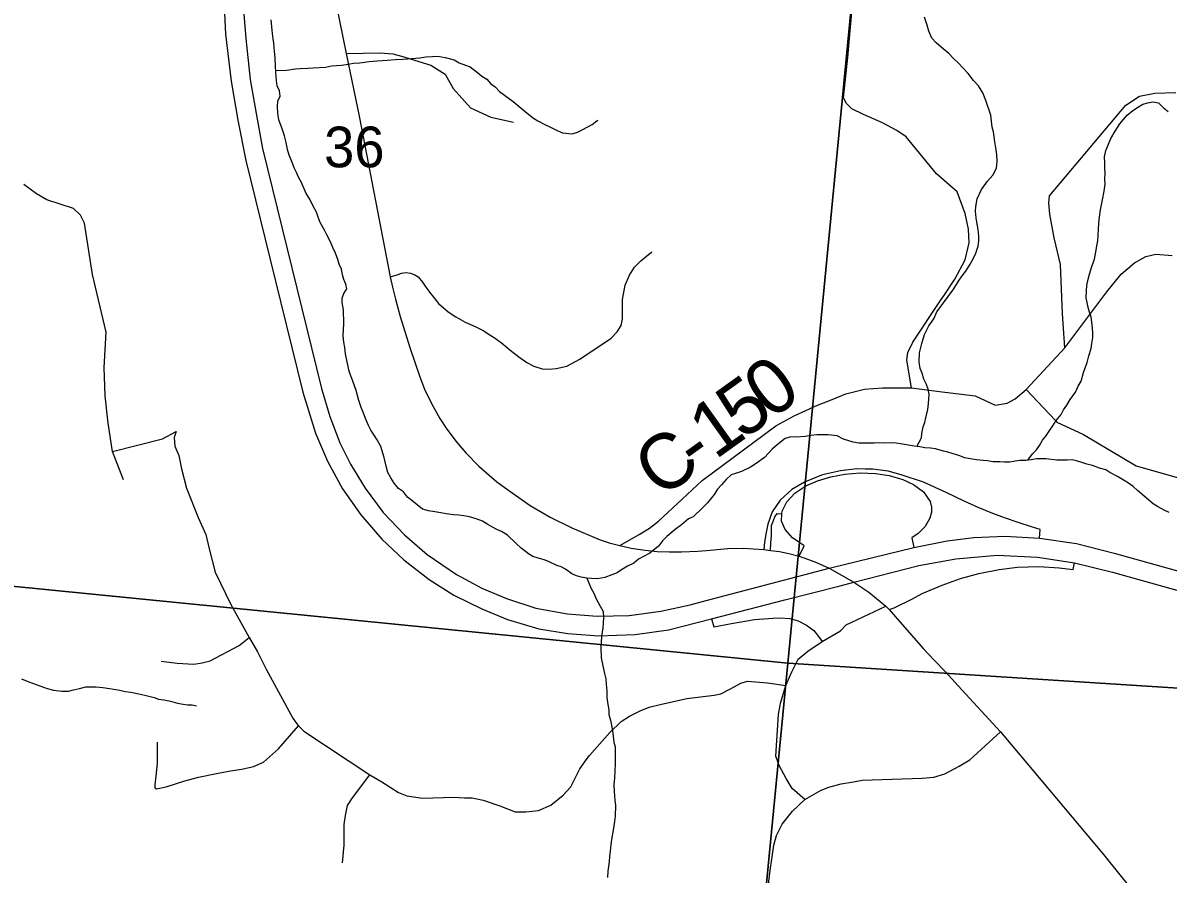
# Model space of a CAD drawing. Extents: x 0 to 34, y 0 to 22.
# Drawn here: x 5.48 to 6.66, y 15.894 to 16.77 of the extents above; entities that cross this region are included whole.
import ezdxf

# ---------------------------------------------------------------- set-up
doc = ezdxf.new("R2010")
doc.units = 0
for name, color, linetype in [('GM_X_County_Road', 7, 'Continuous'), ('GM_X_County_Road_Text', 7, 'Continuous'), ('GM_X_Interchange_Ramps', 7, 'Continuous'), ('GM_X_Interstate_Route', 7, 'Continuous'), ('GM_X_Minor_River', 7, 'Continuous'), ('GM_X_Section', 7, 'Continuous'), ('GM_X_Section_Text', 7, 'Continuous'), ('GM_X_Township_Road', 7, 'Continuous'), ('GM_X_US_Route', 7, 'Continuous')]:
    doc.layers.add(name, color=color, linetype=linetype)

msp = doc.modelspace()

# ---------------------------------------------------------------- linework, layer by layer
at = {"layer": 'GM_X_County_Road'}
for p, q in [((6.5133, 16.3926), (6.5435, 16.3606)), ((6.2433, 16.2278), (6.2501, 16.227))]:
    msp.add_line(p, q, dxfattribs=at)
for points in [[(5.7859, 16.8717), (5.8131, 16.7386), (5.8262, 16.674), (5.8583, 16.5087), (5.8607, 16.498), (5.8638, 16.4855), (5.8685, 16.4679), (5.8785, 16.436), (5.8888, 16.4057), (5.8937, 16.3929), (5.8977, 16.3843), (5.9025, 16.375), (5.9094, 16.3629), (5.9158, 16.3527), (5.9258, 16.3393), (5.9362, 16.3274), (5.9495, 16.3137), (5.968, 16.2976), (5.9814, 16.2878), (6.0025, 16.2733), (6.023, 16.2611), (6.0453, 16.2503), (6.0746, 16.2378), (6.0838, 16.2346), (6.0947, 16.232), (6.1065, 16.2292), (6.121, 16.2271), (6.1334, 16.2259), (6.1455, 16.2253), (6.1585, 16.2254), (6.1752, 16.2262), (6.1879, 16.2272), (6.2061, 16.2289), (6.2218, 16.2292), (6.2433, 16.2278)], [(6.5531, 16.4354), (6.5509, 16.4708), (6.5487, 16.5214), (6.5421, 16.5489), (6.5379, 16.5733), (6.5368, 16.5844), (6.5374, 16.592), (6.6159, 16.6855), (6.6302, 16.6945), (6.6459, 16.6978), (6.6675, 16.6983)], [(6.5531, 16.4354), (6.5964, 16.4932), (6.6113, 16.5114), (6.625, 16.5231), (6.6366, 16.5295), (6.6469, 16.5319), (6.6639, 16.5306)], [(6.3073, 16.3799), (6.3135, 16.3824), (6.3275, 16.388), (6.3467, 16.3928), (6.3655, 16.3944), (6.3954, 16.3944), (6.4242, 16.3904), (6.4609, 16.386), (6.4815, 16.3766), (6.4937, 16.3785), (6.5022, 16.3831), (6.5133, 16.3926), (6.5531, 16.4354)], [(6.0947, 16.232), (6.1148, 16.2434), (6.1254, 16.2499), (6.1347, 16.2571), (6.159, 16.2797), (6.1797, 16.2989), (6.2329, 16.3384), (6.2556, 16.3552), (6.2744, 16.3656), (6.2984, 16.3764), (6.3073, 16.3799)], [(6.5435, 16.3606), (6.545, 16.359), (6.5723, 16.3462), (6.6266, 16.314), (6.6726, 16.3011)], [(6.2501, 16.227), (6.2594, 16.2257), (6.2688, 16.2237), (6.2794, 16.221), (6.2893, 16.2177), (6.2973, 16.2146), (6.3104, 16.2087), (6.3359, 16.1942), (6.3512, 16.1838), (6.3687, 16.1696), (6.3722, 16.166), (6.381, 16.1561), (6.4076, 16.1255), (6.419, 16.1137)], [(6.3032, 16.133), (6.3223, 16.1442), (6.3281, 16.1503), (6.3687, 16.1696)], [(6.26, 16.0675), (6.2603, 16.0695), (6.2658, 16.0877), (6.2719, 16.1019), (6.2787, 16.115), (6.2884, 16.1231), (6.3032, 16.133)], [(6.419, 16.1137), (6.4303, 16.1019), (6.4435, 16.0876), (6.4868, 16.04), (6.5286, 15.9906), (6.593, 15.914), (6.6126, 15.8896), (6.6359, 15.861), (6.6545, 15.8376), (6.675, 15.8077)], [(6.2854, 15.9703), (6.2722, 15.9818), (6.2662, 15.9921), (6.2591, 16.0054), (6.2554, 16.0151), (6.2582, 16.0581), (6.26, 16.0675)], [(6.2854, 15.9703), (6.3024, 15.98), (6.3101, 15.9833), (6.323, 15.9865), (6.3357, 15.9888), (6.3445, 15.9904), (6.4064, 15.9923), (6.4182, 15.9934), (6.4297, 15.9969), (6.4443, 16.0047), (6.4554, 16.0112), (6.4868, 16.04)], [(6.2452, 15.8706), (6.2479, 15.883), (6.2495, 15.8948), (6.2517, 15.9115), (6.2536, 15.9234), (6.2562, 15.9334), (6.2622, 15.9451), (6.2726, 15.9583), (6.2854, 15.9703)]]:
    msp.add_lwpolyline(points, dxfattribs=at)
at = {"layer": 'GM_X_Interchange_Ramps'}
for points in [[(6.3066, 16.3053), (6.3025, 16.3044), (6.2851, 16.2971), (6.272, 16.2896), (6.26, 16.2788), (6.2519, 16.2666), (6.2472, 16.2541), (6.2456, 16.2453), (6.244, 16.2353), (6.2433, 16.2278)], [(6.2794, 16.221), (6.2848, 16.2318), (6.2728, 16.2399), (6.2651, 16.2483), (6.2615, 16.2572), (6.2618, 16.2646), (6.2619, 16.2672), (6.2668, 16.2771), (6.2751, 16.2857), (6.2866, 16.2933), (6.2983, 16.2985), (6.3121, 16.3028), (6.3266, 16.3055), (6.3425, 16.3067), (6.3583, 16.3061), (6.3722, 16.3041), (6.3863, 16.3001), (6.3973, 16.2949), (6.4078, 16.2871), (6.4144, 16.2773), (6.4159, 16.2713), (6.4159, 16.2662), (6.4143, 16.26), (6.4093, 16.2516), (6.402, 16.2443), (6.3956, 16.2399), (6.3976, 16.2299)], [(6.3474, 16.3107), (6.3391, 16.3108), (6.322, 16.309), (6.3066, 16.3053)], [(6.527, 16.2397), (6.5279, 16.2486), (6.5188, 16.2512), (6.505, 16.2556), (6.4911, 16.2604), (6.479, 16.265), (6.464, 16.2711), (6.4494, 16.2776), (6.4309, 16.2865), (6.4077, 16.2971), (6.3847, 16.3049), (6.3712, 16.3085), (6.3556, 16.3105), (6.3474, 16.3107)], [(6.2501, 16.227), (6.2505, 16.2349), (6.2509, 16.242), (6.2509, 16.2474), (6.2512, 16.2525), (6.2523, 16.256), (6.2545, 16.2616), (6.257, 16.2651), (6.2618, 16.2646)], [(6.3722, 16.166), (6.3774, 16.1679), (6.3955, 16.1769), (6.4062, 16.1826), (6.4269, 16.1911), (6.4459, 16.198), (6.4647, 16.203), (6.4855, 16.2074), (6.5044, 16.2097), (6.5263, 16.2103), (6.5473, 16.2091), (6.5619, 16.2072), (6.5632, 16.2143)], [(6.1891, 16.1566), (6.1916, 16.1484), (6.21, 16.1516), (6.2337, 16.1557), (6.248, 16.1569), (6.2528, 16.1571)], [(6.2528, 16.1571), (6.2601, 16.1574), (6.27, 16.1567), (6.2785, 16.1544), (6.287, 16.15), (6.2946, 16.1443), (6.2986, 16.1398), (6.3032, 16.133)]]:
    msp.add_lwpolyline(points, dxfattribs=at)
at = {"layer": 'GM_X_Interstate_Route'}
for p, q in [((6.2649, 16.1761), (6.3217, 16.1906)), ((6.1891, 16.1566), (6.2649, 16.1761))]:
    msp.add_line(p, q, dxfattribs=at)
for points in [[(5.5746, 17.316), (5.6012, 17.2831), (5.6128, 17.2649), (5.6269, 17.2407), (5.6435, 17.2072), (5.6512, 17.1853), (5.6546, 17.1738), (5.658, 17.1627), (5.6648, 17.135), (5.6694, 17.1059), (5.6727, 17.0756), (5.6747, 17.0368), (5.6777, 16.9778), (5.6863, 16.8093), (5.6887, 16.7584), (5.6946, 16.7102), (5.7012, 16.6698), (5.7095, 16.6284), (5.7343, 16.528)], [(5.7052, 16.8084), (5.7095, 16.754), (5.7142, 16.7117), (5.7201, 16.6768), (5.7269, 16.6406), (5.7874, 16.3937), (5.7962, 16.3649), (5.8065, 16.3377), (5.8175, 16.3156), (5.8324, 16.291), (5.8512, 16.266), (5.8729, 16.243), (5.8965, 16.2226), (5.9267, 16.202), (5.9526, 16.1879), (5.9782, 16.1774), (6.0083, 16.1675), (6.041, 16.1616), (6.0714, 16.1592), (6.1043, 16.1598), (6.137, 16.1645), (6.1673, 16.1708), (6.1838, 16.1752), (6.3104, 16.2087), (6.3976, 16.2299), (6.432, 16.2368), (6.4594, 16.2403), (6.4919, 16.2417), (6.527, 16.2397), (6.5651, 16.2339), (6.6042, 16.2241), (6.6816, 16.2026)], [(5.7343, 16.528), (5.7683, 16.3898), (5.7812, 16.3476), (5.7938, 16.3187), (5.8093, 16.2904), (5.828, 16.2634), (5.8497, 16.2386), (5.8725, 16.2171), (5.8986, 16.197), (5.924, 16.1807), (5.9528, 16.1667), (5.9791, 16.1559), (6.0115, 16.1463), (6.0414, 16.1413), (6.0727, 16.1391), (6.1105, 16.1404), (6.1449, 16.1452), (6.1891, 16.1566)], [(6.3217, 16.1906), (6.3359, 16.1942), (6.4029, 16.2113), (6.4411, 16.2183), (6.4834, 16.2219), (6.5251, 16.2201), (6.5632, 16.2143)], [(6.5632, 16.2143), (6.6023, 16.2045), (6.6797, 16.183)]]:
    msp.add_lwpolyline(points, dxfattribs=at)
at = {"layer": 'GM_X_Minor_River'}
for points in [[(6.4007, 16.334), (6.4055, 16.3427), (6.406, 16.3472), (6.4074, 16.354), (6.409, 16.3585), (6.41, 16.3634), (6.4122, 16.3721), (6.4127, 16.3782), (6.4133, 16.3827), (6.4135, 16.3876), (6.4125, 16.393), (6.4108, 16.3976), (6.4079, 16.4034), (6.4062, 16.4095), (6.4041, 16.4142), (6.4032, 16.421), (6.4035, 16.4305), (6.4058, 16.44), (6.4087, 16.4493), (6.4132, 16.4583), (6.4184, 16.4654), (6.4213, 16.4725), (6.4261, 16.4791), (6.4329, 16.4884), (6.4388, 16.4962), (6.4437, 16.504), (6.4476, 16.5096), (6.4512, 16.5144), (6.4557, 16.5218), (6.4589, 16.527), (6.4614, 16.533), (6.4639, 16.5401), (6.4648, 16.5458), (6.4646, 16.5504), (6.4641, 16.5572), (6.4625, 16.5649), (6.4619, 16.5695), (6.4613, 16.5763), (6.4615, 16.5809), (6.4629, 16.5888), (6.4674, 16.5985), (6.4734, 16.6071), (6.4789, 16.6133), (6.483, 16.6204), (6.4836, 16.6272), (6.4831, 16.6345), (6.4825, 16.6394), (6.4812, 16.6475), (6.4797, 16.6578), (6.4784, 16.6628), (6.4769, 16.675), (6.4717, 16.6903), (6.4686, 16.6981), (6.4643, 16.7054), (6.4591, 16.7109), (6.4537, 16.7179), (6.4434, 16.7289), (6.4386, 16.7333), (6.4339, 16.7384), (6.4258, 16.7451), (6.4206, 16.7495), (6.4162, 16.7542), (6.413, 16.7615), (6.4114, 16.7677), (6.4086, 16.7761)], [(5.7402, 16.7259), (5.7397, 16.7339), (5.7392, 16.7408), (5.7384, 16.7492), (5.7378, 16.7538), (5.7372, 16.7591), (5.7363, 16.766), (5.7358, 16.7732)], [(5.7403, 16.7212), (5.7514, 16.7214), (5.7606, 16.7226), (5.7656, 16.7232), (5.7735, 16.7236), (5.7789, 16.7238), (5.7918, 16.7245), (5.7979, 16.7258), (5.8082, 16.7266), (5.8128, 16.7272), (5.8204, 16.7285), (5.8269, 16.729), (5.8368, 16.7302), (5.8448, 16.7311), (5.8551, 16.7318), (5.8638, 16.7323), (5.8714, 16.7328), (5.876, 16.733), (5.8889, 16.7341), (5.895, 16.735), (5.9019, 16.7355), (5.9072, 16.7357), (5.9148, 16.7343), (5.9242, 16.7321), (5.9294, 16.7289), (5.9358, 16.7264), (5.9406, 16.7247), (5.9484, 16.7191), (5.9528, 16.7152), (5.9577, 16.7123), (5.9617, 16.7076), (5.9665, 16.7044), (5.9709, 16.6993), (5.9761, 16.6957), (5.985, 16.689), (5.9931, 16.6822), (5.9994, 16.6771), (6.006, 16.6719), (6.0105, 16.6691), (6.0183, 16.665), (6.0228, 16.663), (6.0302, 16.6593), (6.0359, 16.6568), (6.0457, 16.6557), (6.0514, 16.6574), (6.0569, 16.6603), (6.0665, 16.6656), (6.0712, 16.6693), (6.0724, 16.67)], [(6.055, 16.1994), (6.0502, 16.2007), (6.0453, 16.2028), (6.039, 16.2076), (6.0345, 16.21), (6.03, 16.2113), (6.0214, 16.2154), (6.0169, 16.2171), (6.0098, 16.2192), (6.0053, 16.2205), (6.0008, 16.2234), (5.9931, 16.2293), (5.9879, 16.2341), (5.9791, 16.2427), (5.9731, 16.2463), (5.9683, 16.2484), (5.9638, 16.2508), (5.959, 16.2537), (5.9534, 16.2569), (5.947, 16.2594), (5.9399, 16.2616), (5.9342, 16.2625), (5.9289, 16.2631), (5.924, 16.2636), (5.9161, 16.2647), (5.9104, 16.2656), (5.9044, 16.2666), (5.8976, 16.2676), (5.8915, 16.2693), (5.886, 16.2737), (5.8805, 16.2784), (5.876, 16.2816), (5.872, 16.2871), (5.8668, 16.2907), (5.8625, 16.2961), (5.8589, 16.3016), (5.856, 16.307), (5.854, 16.3135), (5.852, 16.3227), (5.8486, 16.3339), (5.845, 16.3408), (5.8418, 16.3455), (5.8382, 16.3509), (5.836, 16.3556), (5.8329, 16.3629), (5.8304, 16.3691), (5.8283, 16.3741), (5.8259, 16.3814), (5.8232, 16.3917), (5.8194, 16.4021), (5.817, 16.4083), (5.8156, 16.4129), (5.8137, 16.4228), (5.8124, 16.4293), (5.8115, 16.4358), (5.8105, 16.4412), (5.81, 16.448), (5.8104, 16.4606), (5.8102, 16.4746), (5.8089, 16.4823), (5.8087, 16.4868), (5.8107, 16.4913), (5.8135, 16.4962), (5.8126, 16.5011), (5.8105, 16.5058), (5.8091, 16.5108), (5.8082, 16.5165), (5.8057, 16.5215), (5.8043, 16.5265), (5.8019, 16.5331), (5.7991, 16.5388), (5.7963, 16.5454), (5.7931, 16.552), (5.7906, 16.5566), (5.7863, 16.5647), (5.7842, 16.5701), (5.7825, 16.5751), (5.7789, 16.5813), (5.7754, 16.5887), (5.7718, 16.5945), (5.7696, 16.5991), (5.7665, 16.6065), (5.764, 16.6111), (5.7619, 16.6161), (5.7594, 16.6208), (5.7569, 16.6273), (5.7541, 16.6339), (5.7524, 16.6396), (5.7512, 16.6469), (5.7495, 16.6538), (5.7471, 16.6611), (5.7436, 16.6703), (5.7427, 16.6772), (5.7422, 16.6841), (5.7424, 16.6894), (5.7448, 16.6946), (5.7443, 16.7), (5.7418, 16.7054), (5.7412, 16.7107), (5.7404, 16.7191), (5.7402, 16.7259)], [(6.5151, 16.3198), (6.5199, 16.3262), (6.5242, 16.3306), (6.5271, 16.3351), (6.5303, 16.3403), (6.5335, 16.3447), (6.5378, 16.3506), (6.5407, 16.3551), (6.5443, 16.3607), (6.5494, 16.367), (6.5519, 16.3718), (6.5554, 16.3766), (6.5587, 16.3822), (6.5643, 16.39), (6.5671, 16.396), (6.57, 16.4012), (6.5725, 16.4102), (6.5763, 16.4204), (6.5781, 16.4271), (6.5802, 16.4347), (6.5812, 16.44), (6.5821, 16.446), (6.5819, 16.4513), (6.5814, 16.4593), (6.5802, 16.467), (6.5785, 16.4723), (6.5771, 16.4769), (6.5762, 16.4823), (6.5752, 16.4869), (6.5754, 16.4941), (6.576, 16.4998), (6.5774, 16.5062), (6.5787, 16.5115), (6.5812, 16.5194), (6.5838, 16.5269), (6.5856, 16.5359), (6.5861, 16.5405), (6.5871, 16.5458), (6.5876, 16.5511), (6.5879, 16.5579), (6.5884, 16.5632), (6.5886, 16.5677), (6.5901, 16.5776), (6.5919, 16.5878), (6.5938, 16.5968), (6.5948, 16.604), (6.5946, 16.6093), (6.5948, 16.6154), (6.5946, 16.6204), (6.5944, 16.6261), (6.5942, 16.6321), (6.5956, 16.6386), (6.5981, 16.6453), (6.6006, 16.6509), (6.605, 16.6587), (6.6098, 16.6662), (6.6138, 16.6706), (6.6173, 16.675), (6.6232, 16.6798), (6.629, 16.6838), (6.6337, 16.6863), (6.6387, 16.6876), (6.644, 16.6889), (6.6497, 16.6876), (6.6544, 16.6829), (6.6596, 16.6789)], [(6.6606, 16.2658), (6.6554, 16.2683), (6.6487, 16.272), (6.6442, 16.2748), (6.635, 16.2827), (6.628, 16.2886), (6.6235, 16.2926), (6.6187, 16.2962), (6.6143, 16.299), (6.6076, 16.303), (6.5997, 16.3071), (6.5953, 16.3099), (6.5889, 16.3116), (6.5818, 16.3142), (6.5758, 16.3159), (6.5709, 16.3176), (6.5652, 16.3193), (6.5607, 16.3202), (6.5558, 16.32), (6.5512, 16.3198), (6.5451, 16.32), (6.5338, 16.3212), (6.5292, 16.3213), (6.5239, 16.3211), (6.5186, 16.3202), (6.5132, 16.3196), (6.5068, 16.3194), (6.5022, 16.3188), (6.4965, 16.3179), (6.4912, 16.3177), (6.4862, 16.3182), (6.4794, 16.3181), (6.4737, 16.3191), (6.4692, 16.3196), (6.4624, 16.3202), (6.4556, 16.3212), (6.4503, 16.3221), (6.4439, 16.3246), (6.4372, 16.3268), (6.4327, 16.3281), (6.4281, 16.329), (6.4199, 16.3316), (6.415, 16.3321), (6.4089, 16.3327), (6.404, 16.3336), (6.3979, 16.3342), (6.384, 16.3366), (6.3795, 16.3375), (6.3745, 16.3377), (6.3677, 16.3375), (6.3612, 16.3378), (6.3567, 16.3375), (6.351, 16.3374), (6.346, 16.3372), (6.3411, 16.3373), (6.3351, 16.3383), (6.3253, 16.3413), (6.3186, 16.3449), (6.3095, 16.346), (6.2977, 16.346), (6.292, 16.3451), (6.2859, 16.3442), (6.2764, 16.3437), (6.2711, 16.3439), (6.265, 16.3422), (6.2568, 16.3357), (6.2517, 16.3313), (6.2438, 16.3225), (6.2352, 16.3163), (6.2294, 16.3127), (6.2201, 16.3081), (6.214, 16.306), (6.2094, 16.3047), (6.2043, 16.2999), (6.1995, 16.2944), (6.1956, 16.2899), (6.192, 16.2844), (6.1852, 16.2759), (6.1801, 16.2707), (6.1703, 16.2616), (6.1657, 16.2594), (6.1583, 16.2532), (6.152, 16.2485), (6.1434, 16.2412), (6.1387, 16.2368), (6.1347, 16.2313), (6.1257, 16.224), (6.1192, 16.2208), (6.1142, 16.2179), (6.1091, 16.2139), (6.1029, 16.2107), (6.0967, 16.2071), (6.092, 16.2039), (6.0866, 16.2018), (6.0793, 16.199), (6.0717, 16.1977), (6.0656, 16.1979), (6.0607, 16.1985), (6.055, 16.1994)], [(6.0607, 16.1985), (6.0653, 16.1877), (6.0682, 16.183), (6.0706, 16.1772), (6.0745, 16.1695), (6.0778, 16.1641), (6.0779, 16.158), (6.0777, 16.1523), (6.0772, 16.147), (6.0761, 16.1391), (6.0755, 16.1319), (6.0753, 16.1266), (6.0757, 16.1163), (6.0777, 16.1063), (6.079, 16.1002), (6.0803, 16.0948), (6.0809, 16.0891), (6.0814, 16.0823), (6.0815, 16.0754), (6.0824, 16.0682), (6.0834, 16.0628), (6.0836, 16.0579), (6.0853, 16.0521), (6.0866, 16.0452), (6.0875, 16.0388), (6.0887, 16.0296), (6.09, 16.0246), (6.0902, 16.017), (6.0902, 16.0071), (6.0896, 15.9995), (6.0893, 15.9927), (6.0887, 15.9855), (6.0889, 15.9791), (6.0897, 15.9695), (6.0903, 15.9646), (6.0899, 15.9532), (6.0893, 15.9479), (6.0879, 15.9388), (6.0864, 15.9294), (6.0855, 15.9241), (6.0848, 15.9173), (6.0843, 15.912), (6.0837, 15.9063), (6.0826, 15.8968), (6.082, 15.89)], [(5.4786, 16.0948), (5.486, 16.0915), (5.5048, 16.0847), (5.5116, 16.083), (5.5199, 16.0819), (5.5271, 16.0821), (5.5321, 16.0834), (5.5382, 16.0847), (5.5447, 16.0864), (5.5508, 16.0866), (5.5553, 16.0864), (5.5622, 16.0858), (5.569, 16.0848), (5.5735, 16.0839), (5.5799, 16.0829), (5.5852, 16.0816), (5.5912, 16.081), (5.5995, 16.0792), (5.6055, 16.0778), (5.6153, 16.0756), (5.6198, 16.0739), (5.6251, 16.073), (5.6319, 16.0716), (5.6391, 16.0698), (5.6451, 16.0685), (5.6496, 16.068), (5.6542, 16.0678), (5.6587, 16.0669)]]:
    msp.add_lwpolyline(points, dxfattribs=at)
at = {"layer": 'GM_X_Section'}
for points in [[(5.3785, 17.205), (6.3631, 17.0951), (6.268, 16.1109), (5.2813, 16.2088)], [(7.2711, 17.0443), (7.2064, 16.0507), (6.268, 16.1109), (6.3631, 17.0951)], [(6.268, 16.1109), (6.1715, 15.1151), (5.1838, 15.2208), (5.2813, 16.2088)], [(7.2064, 16.0507), (7.1496, 15.0512), (6.1715, 15.1151), (6.268, 16.1109)]]:
    msp.add_lwpolyline(points, close=True, dxfattribs=at)
at = {"layer": 'GM_X_Township_Road'}
msp.add_line((5.5835, 16.2996), (5.5721, 16.3286), dxfattribs=at)
for points in [[(6.3304, 16.7426), (6.3485, 16.9462), (6.3553, 17.0221)], [(5.8131, 16.7386), (5.8481, 16.7392), (5.861, 16.7382), (5.87, 16.7357), (5.9003, 16.7266), (5.9148, 16.7173), (5.9233, 16.7025), (5.941, 16.6826), (5.962, 16.6729), (5.9854, 16.6679)], [(6.4285, 16.4892), (6.4398, 16.5062), (6.4507, 16.526), (6.4547, 16.5437), (6.454, 16.5578), (6.4507, 16.5739), (6.4423, 16.596), (6.4209, 16.6148), (6.3898, 16.6526), (6.3802, 16.6593), (6.3655, 16.6673), (6.346, 16.6759), (6.3338, 16.6817), (6.3282, 16.687), (6.3253, 16.693), (6.3299, 16.7378), (6.3304, 16.7426)], [(5.5721, 16.3286), (5.5678, 16.358), (5.5648, 16.386), (5.5637, 16.4152), (5.5659, 16.4517), (5.5518, 16.511), (5.5433, 16.5639), (5.5392, 16.572), (5.5322, 16.5791), (5.5045, 16.588), (5.4938, 16.5941), (5.4808, 16.6036)], [(5.8583, 16.5087), (5.8656, 16.5108), (5.87, 16.5123), (5.8747, 16.5129), (5.8792, 16.5123), (5.8836, 16.5108), (5.887, 16.5085), (5.8917, 16.5032), (5.8944, 16.4991), (5.8987, 16.4928), (5.9031, 16.4873), (5.908, 16.4813), (5.9181, 16.4725), (5.9259, 16.4675), (5.9354, 16.462), (5.9458, 16.4575), (5.9549, 16.4529), (5.9602, 16.4494), (5.9653, 16.4461), (5.9731, 16.4405), (5.9816, 16.4333), (5.9909, 16.4261), (5.9989, 16.4203), (6.0061, 16.4165), (6.0148, 16.414), (6.0221, 16.4136), (6.0293, 16.4141), (6.0404, 16.4165), (6.0538, 16.424), (6.0859, 16.4454), (6.0921, 16.452), (6.0961, 16.4585), (6.0976, 16.4655), (6.0976, 16.4853), (6.1002, 16.5), (6.1048, 16.5104), (6.1099, 16.5186), (6.1166, 16.5251), (6.1223, 16.5298), (6.1278, 16.5342)], [(6.3954, 16.3944), (6.3905, 16.4228), (6.3915, 16.4307), (6.3968, 16.4412), (6.4253, 16.4843), (6.4285, 16.4892)], [(5.5721, 16.3286), (5.6237, 16.3417), (5.638, 16.3492)], [(5.638, 16.3492), (5.6359, 16.3433), (5.6365, 16.3341), (5.6405, 16.3246), (5.6432, 16.3108), (5.6485, 16.2909), (5.6606, 16.2609), (5.6685, 16.2434), (5.6717, 16.2285), (5.6779, 16.2047), (5.694, 16.1713), (5.7129, 16.1373), (5.7216, 16.1226), (5.7305, 16.1047), (5.7579, 16.0543), (5.762, 16.0485), (5.7637, 16.0462), (5.7692, 16.0407), (5.8372, 15.996), (5.8496, 15.9885), (5.8669, 15.9778), (5.8756, 15.9744), (5.8917, 15.9718), (5.9238, 15.9729), (5.9347, 15.9723), (5.9428, 15.9721), (5.954, 15.9697), (5.9711, 15.964), (5.9872, 15.9579), (5.9936, 15.9576), (5.9979, 15.9576), (6.0109, 15.9591), (6.0236, 15.9646), (6.0365, 15.9749), (6.0443, 15.9836), (6.0538, 16.0021), (6.0602, 16.0113), (6.0636, 16.0156), (6.0847, 16.0395), (6.0962, 16.0508), (6.1049, 16.0563), (6.1158, 16.0618), (6.1251, 16.0655), (6.1363, 16.0684), (6.164, 16.0744), (6.192, 16.0779), (6.1989, 16.0793), (6.209, 16.0845), (6.2194, 16.0903), (6.2263, 16.0923), (6.2468, 16.0906), (6.2658, 16.0877)], [(5.6223, 16.1128), (5.6389, 16.1109), (5.6562, 16.1099), (5.6647, 16.1111), (5.673, 16.1133), (5.7027, 16.1289), (5.7129, 16.1373)], [(5.6184, 16.0296), (5.6182, 16.0079), (5.6169, 15.9945), (5.6157, 15.9855), (5.6157, 15.9826), (5.6177, 15.9816), (5.6277, 15.9835), (5.6467, 15.9896), (5.6608, 15.9935), (5.6793, 15.9974), (5.6939, 16.0001), (5.7056, 16.0018), (5.7175, 16.0045), (5.7277, 16.0089), (5.7433, 16.0225), (5.7637, 16.0462)], [(5.8093, 15.9054), (5.811, 15.9233), (5.811, 15.9343), (5.811, 15.9447), (5.8121, 15.9539), (5.8144, 15.9643), (5.8196, 15.9723), (5.8372, 15.996)]]:
    msp.add_lwpolyline(points, dxfattribs=at)
at = {"layer": 'GM_X_US_Route'}
for p, q in [((6.2649, 16.1761), (6.3217, 16.1906)), ((6.1891, 16.1566), (6.2649, 16.1761))]:
    msp.add_line(p, q, dxfattribs=at)
for points in [[(5.5746, 17.316), (5.6012, 17.2831), (5.6128, 17.2649), (5.6269, 17.2407), (5.6435, 17.2072), (5.6512, 17.1853), (5.6546, 17.1738), (5.658, 17.1627), (5.6648, 17.135), (5.6694, 17.1059), (5.6727, 17.0756), (5.6747, 17.0368), (5.6777, 16.9778), (5.6863, 16.8093), (5.6887, 16.7584), (5.6946, 16.7102), (5.7012, 16.6698), (5.7095, 16.6284), (5.7343, 16.528)], [(5.7343, 16.528), (5.7683, 16.3898), (5.7812, 16.3476), (5.7938, 16.3187), (5.8093, 16.2904), (5.828, 16.2634), (5.8497, 16.2386), (5.8725, 16.2171), (5.8986, 16.197), (5.924, 16.1807), (5.9528, 16.1667), (5.9791, 16.1559), (6.0115, 16.1463), (6.0414, 16.1413), (6.0727, 16.1391), (6.1105, 16.1404), (6.1449, 16.1452), (6.1891, 16.1566)], [(6.3217, 16.1906), (6.3359, 16.1942), (6.4029, 16.2113), (6.4411, 16.2183), (6.4834, 16.2219), (6.5251, 16.2201), (6.5632, 16.2143)], [(6.5632, 16.2143), (6.6023, 16.2045), (6.6797, 16.183)]]:
    msp.add_lwpolyline(points, dxfattribs=at)

# ---------------------------------------------------------------- texts
at = {"layer": 'GM_X_County_Road_Text'}
for s, rotation, p in [('0', 36.3906, (6.2502, 16.3606)), ('5', 35.659, (6.2213, 16.3399)), ('1', 35.5639, (6.193, 16.3197)), ('C', 35.5532, (6.1365, 16.2793)), ('-', 35.5532, (6.1742, 16.3062))]:
    msp.add_text(s, height=0.0568, rotation=rotation, dxfattribs=at).set_placement(p)
at = {"layer": 'GM_X_Section_Text'}
msp.add_text('36', height=0.04186, rotation=0, dxfattribs=at).set_placement((5.7902, 16.6214))

doc.saveas('drawing.dxf')
